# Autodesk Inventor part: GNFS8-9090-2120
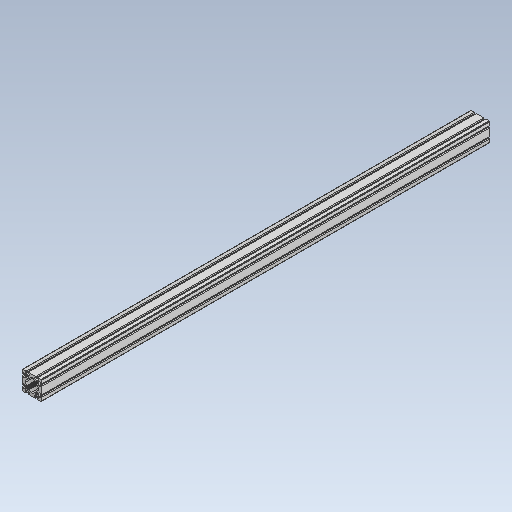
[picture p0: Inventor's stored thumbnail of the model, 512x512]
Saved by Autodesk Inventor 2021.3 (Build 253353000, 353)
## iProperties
Created: 2022-02
Part Number: GNFS8-9090-2120
Material: 一般
Document SubType Name: Modeling
Designer: kengo
Density: 1 g/cm^3
Appearance: 既定
Author: kengo
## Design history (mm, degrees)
feature "GNFS8-9090-2120"
node "ソリッド1"
